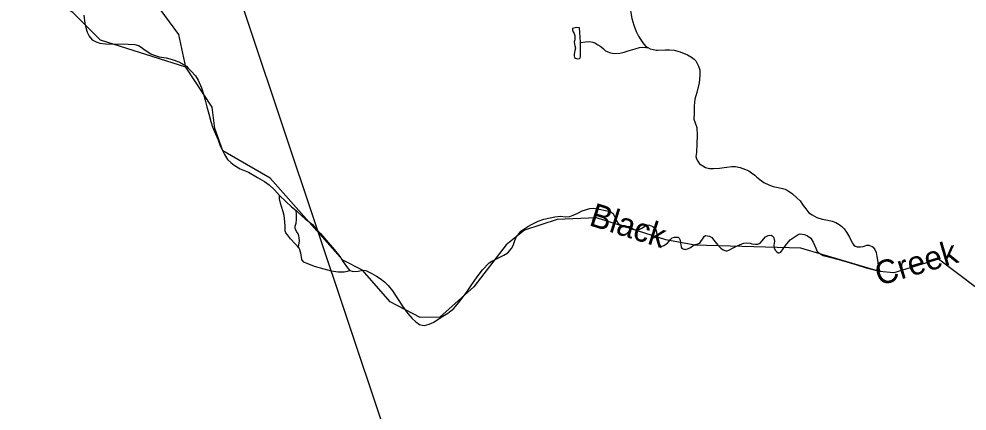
# Model space of a CAD drawing. Extents: x 2082433 to 2279600, y 546599 to 755198.
# Drawn here: x 2153161 to 2159193, y 625157 to 627650 of the extents above; entities that cross this region are included whole.
import ezdxf

# ---------------------------------------------------------------- set-up
doc = ezdxf.new("R2010")
doc.units = 0
for name, color, linetype in [('Exist Boundary Political Fire Districts', 7, 'Continuous'), ('Exist Hydrographic Creek Single Shore', 7, 'Continuous'), ('Exist Hydrographic Creek Single Shore Label', 7, 'Continuous'), ('Exist Hydrographic Misc Water Feature', 7, 'Continuous')]:
    doc.layers.add(name, color=color, linetype=linetype)

msp = doc.modelspace()

# ---------------------------------------------------------------- linework, layer by layer
at = {"layer": 'Exist Boundary Political Fire Districts'}
msp.add_lwpolyline([(2153751.2, 618762.9), (2155677.9, 624465.5), (2154003, 629468)], dxfattribs=at)
at = {"layer": 'Exist Hydrographic Creek Single Shore'}
for points in [[(2154221.5, 627344.2), (2154178.5, 627551.7), (2154028.6, 627751.6), (2153968.5, 627910.3), (2153975.5, 628257.9), (2154114.5, 628642.1), (2154453.5, 629035.5), (2154577.5, 629328.2), (2154576.5, 629446.3)], [(2154221.5, 627344.2), (2153679.6, 627516), (2153503.4, 627690.1), (2153411.6, 627747.7), (2153228.5, 627764.6), (2152503.4, 627759.6), (2152204.4, 627683.7), (2151820.3, 627806.3), (2151644.4, 627954.2), (2151410.4, 628070.5), (2151068.4, 628133.2), (2150709.4, 628340.5), (2150459.4, 628365.3), (2150300.5, 628404.6), (2150116.3, 628513.4), (2149924.4, 628687.8), (2149782.3, 628759.6), (2149523.3, 628751.8), (2149273.4, 628815.9), (2148940.4, 628730.7)], [(2159252.5, 625939.8), (2159010.6, 626121.9), (2158727.6, 626035.7), (2158635.5, 626044.1), (2158135.6, 626192.1), (2157460.6, 626212.3), (2157276.6, 626245.6), (2156834.5, 626385.8), (2156584.6, 626374.5), (2156376.4, 626306.6), (2156260.6, 626213.7), (2156054.5, 625945.7), (2155838.6, 625753.2), (2155713.5, 625752.5), (2155521.6, 625851.5), (2155345.4, 626051.9), (2155220.6, 626116.8), (2154758.6, 626637.9), (2154457.5, 626811.3), (2154407.5, 626953.3), (2154389.5, 627088.2), (2154221.5, 627344.2)]]:
    msp.add_lwpolyline(points, dxfattribs=at)
at = {"layer": 'Exist Hydrographic Misc Water Feature'}
for points in [[(2153573.2, 627673.6), (2153579.4, 627621.5), (2153585.8, 627595.4), (2153594, 627565.8), (2153607.9, 627539.8), (2153626.4, 627517.9), (2153652, 627503.9), (2153676.2, 627496.1), (2153712.1, 627492.3), (2153856.2, 627489.2), (2153898.3, 627487.3), (2153920.4, 627481.6), (2153938.2, 627471.5), (2153964.7, 627451.7), (2154000.4, 627428.1), (2154014.1, 627422), (2154052.5, 627410.1), (2154098.4, 627402.3), (2154134.7, 627392.8), (2154178.8, 627376.8), (2154226.9, 627349.2), (2154237.2, 627337.1)], [(2157052, 627704.8), (2157054, 627689.1), (2157060.2, 627652.9), (2157072.3, 627610.9), (2157086.6, 627569.4), (2157102.8, 627541.4), (2157117.2, 627517.4), (2157130.7, 627497.4), (2157147.1, 627477.5), (2157161, 627467.7)], [(2156733.3, 627499.2), (2156730.6, 627535.2), (2156726.7, 627593), (2156708.9, 627594.9), (2156682.9, 627589.1), (2156682.9, 627579), (2156686.5, 627569), (2156692.7, 627557.2), (2156697.2, 627543.1), (2156697.2, 627524.9), (2156697.2, 627517.1), (2156693.1, 627505.2), (2156695.4, 627491.1), (2156697.2, 627479.1), (2156701.5, 627465), (2156697.2, 627449), (2156693.7, 627425.2), (2156693.7, 627413), (2156695.8, 627405), (2156701.5, 627400.9), (2156713.6, 627397), (2156727.6, 627399.4), (2156731.7, 627403.2), (2156733.9, 627411.4), (2156733.3, 627499.2)], [(2156733.3, 627499.2), (2156764.9, 627505.3), (2156789.1, 627505.7), (2156811.4, 627501.5), (2156825.2, 627497.8), (2156843.2, 627485.8), (2156862.9, 627473.8), (2156879.3, 627460), (2156891.4, 627448), (2156907.4, 627440.4), (2156923.4, 627434.3), (2156949.6, 627430.3), (2156983.5, 627432.5), (2157011.4, 627438.8), (2157037.4, 627447.1), (2157081.5, 627459.1), (2157109.2, 627467.4), (2157127.4, 627469.6), (2157149.1, 627467.5), (2157161, 627467.7)], [(2157161, 627467.7), (2157177.2, 627459.6), (2157195.3, 627455.6), (2157217.2, 627451.9), (2157223.2, 627452.2), (2157273.2, 627454.4), (2157299.2, 627454.6), (2157329.2, 627450.8), (2157367.1, 627441), (2157413.5, 627421), (2157439.7, 627407.3), (2157455.5, 627395.2), (2157467.6, 627383.2), (2157477.8, 627363.5), (2157484, 627349.5), (2157492, 627325.6), (2157492.2, 627289.5), (2157488.5, 627243.4), (2157472.9, 627183.3), (2157460.8, 627139.3), (2157457.3, 627097.3), (2157455.5, 627073.6), (2157455.7, 627049.6), (2157453.4, 627013.5), (2157463.5, 626989.7), (2157473.9, 626959.7), (2157476.2, 626909.5), (2157474.4, 626855.4), (2157470.9, 626801.6), (2157467, 626775.4), (2157471.1, 626761.4), (2157479.5, 626745.5), (2157491.2, 626729.5), (2157511.1, 626716), (2157529.3, 626706), (2157553.5, 626699.9), (2157579.6, 626698.4), (2157617.3, 626700.4), (2157647.4, 626704.7), (2157665.1, 626706.9), (2157695.2, 626710.9), (2157719.4, 626710.9), (2157748.9, 626705.2), (2157783.2, 626693.6), (2157805.3, 626683.7), (2157821.5, 626671.5), (2157841.6, 626655.9), (2157855.8, 626644), (2157873.4, 626628), (2157899.8, 626610.2), (2157932, 626594.4), (2157960.1, 626584.5), (2157989.9, 626578.8), (2158017.7, 626570.9), (2158035.8, 626566.9), (2158054, 626556.8), (2158082.3, 626537.2), (2158112.5, 626511.2), (2158130.7, 626493.4), (2158150.4, 626463.6), (2158166.6, 626441.7), (2158186.5, 626417.6), (2158206.8, 626404), (2158236.7, 626388.1), (2158271, 626376.4), (2158307.1, 626370.6), (2158335, 626364.8), (2158358.7, 626354.7), (2158379.5, 626343), (2158395.2, 626330.9), (2158411.2, 626315.1), (2158425.4, 626295.1), (2158445.5, 626263.3), (2158461.7, 626227.2), (2158467.6, 626217.3), (2158471.7, 626211.4), (2158481.8, 626205.5), (2158493.9, 626201.6), (2158514, 626199.8), (2158531.6, 626203.6), (2158555.6, 626211.8), (2158567.5, 626212), (2158589.6, 626202.1), (2158595.8, 626198), (2158606.2, 626184.2), (2158614, 626164.4), (2158617.9, 626140.3), (2158622.2, 626116.5), (2158628.2, 626084.4), (2158634.5, 626056.3), (2158636.8, 626048.6)], [(2154237.2, 627337.1), (2154256.9, 627317.5), (2154283.3, 627287.5), (2154301.2, 627259.7), (2154321.7, 627211.6), (2154334.2, 627172), (2154345.7, 627134.2), (2154356.1, 627092), (2154368.4, 627045.9), (2154380.9, 626998.3), (2154392.6, 626964.4), (2154411.3, 626920.2), (2154427.5, 626880.5), (2154441.6, 626842.6), (2154468.1, 626788.8), (2154488.2, 626756.9), (2154508.3, 626736.9), (2154530.2, 626721), (2154568.4, 626697.4), (2154620.4, 626675.7), (2154678.7, 626642.2), (2154723.2, 626616.4), (2154752.7, 626594.5), (2154787.4, 626562.5), (2154819.1, 626526.8)], [(2154819.1, 626526.8), (2154859.3, 626489.1), (2154895.6, 626455.2), (2154923.7, 626431.6)], [(2154937.3, 626199.5), (2154932.7, 626205.5), (2154919, 626219.7), (2154888.9, 626251.5), (2154868.6, 626277.2), (2154858.7, 626289.3), (2154854.2, 626302.9), (2154854.4, 626317.1), (2154854.4, 626334.9), (2154850.1, 626381), (2154847.6, 626399.2), (2154841.9, 626422.8), (2154831.9, 626456.8), (2154825.7, 626478.8), (2154819.3, 626507), (2154819.1, 626526.8)], [(2154937.3, 626199.5), (2154939.3, 626203.7), (2154940.9, 626213.6), (2154943, 626223.8), (2154944.8, 626239.8), (2154942.6, 626257.5), (2154940.7, 626271.6), (2154936.8, 626283.6), (2154928.6, 626295.3), (2154920.6, 626311.5), (2154918.6, 626321.6), (2154918.2, 626325.3), (2154918.4, 626331.3), (2154920.6, 626339.5), (2154924.3, 626351.5), (2154926.4, 626371.5), (2154927.6, 626407.4), (2154923.7, 626431.6)], [(2154923.7, 626431.6), (2154937.9, 626419.7), (2154982.2, 626379.7), (2155008.2, 626359.9), (2155028.1, 626341.9), (2155056.6, 626308.1), (2155078.3, 626286.5), (2155127.1, 626228.9), (2155166.9, 626183), (2155201.4, 626138.9), (2155223.3, 626105.2), (2155251.4, 626067.3), (2155265.9, 626049.6)], [(2155265.9, 626049.6), (2155279.7, 626045.5), (2155292.2, 626043.7), (2155318, 626045.8), (2155348, 626051.8), (2155367.7, 626050.1), (2155405.8, 626032.2), (2155435.9, 626014.2), (2155458.1, 625998.7), (2155486.2, 625978.6), (2155510.2, 625954.8), (2155536.6, 625921.2), (2155568.6, 625873.3), (2155601, 625823.4), (2155633.2, 625779.6), (2155661.5, 625745.7), (2155685.5, 625723.8), (2155709.7, 625708), (2155725.7, 625702.3), (2155741.7, 625700.3), (2155771.4, 625708.4), (2155799.7, 625722.4), (2155847.3, 625752.9), (2155889.1, 625779), (2155926.8, 625809.4), (2155956.6, 625845.5), (2155980.4, 625873.5), (2156011.9, 625917.8), (2156038, 625954), (2156075.9, 626010), (2156109.1, 626054.4), (2156153, 626098.4), (2156169, 626110.6), (2156183.4, 626116.6), (2156199.1, 626124.7), (2156220.7, 626134.8), (2156244.9, 626147), (2156270.9, 626163), (2156294.7, 626191), (2156304.5, 626209.4), (2156316.2, 626241.3), (2156324.2, 626261.6), (2156334.3, 626275.5), (2156354, 626299.7), (2156397.8, 626329.9), (2156425.9, 626345.9), (2156463.9, 626364.1), (2156499.3, 626376.2), (2156539.5, 626384.3), (2156569.5, 626390.7), (2156605.3, 626395.1), (2156637.5, 626391), (2156665.4, 626393.3), (2156687.2, 626401.4), (2156717.1, 626415.5), (2156745, 626429.5), (2156793.4, 626444.1), (2156817.2, 626446.2), (2156853.1, 626440.4), (2156891.4, 626432.5), (2156925.4, 626422.5), (2156937.1, 626414.6), (2156943.1, 626406.8), (2156955.4, 626382.7), (2156961.5, 626366.8), (2156973.4, 626349.2), (2156983.5, 626343.2), (2156999.5, 626337.1), (2157019.8, 626333.2), (2157045.4, 626329.3), (2157059.9, 626319.4), (2157069.6, 626313.5), (2157083.7, 626309.8), (2157107.5, 626311.9), (2157127.4, 626321.8), (2157145.7, 626334), (2157155.5, 626339.9), (2157171.5, 626338.3), (2157193.4, 626330.1), (2157207.6, 626320.3), (2157211.9, 626310.3), (2157217.8, 626292.3), (2157230.1, 626238.5), (2157234.4, 626218.5), (2157235.9, 626212.6), (2157240, 626206.7), (2157248.4, 626202.6), (2157264.2, 626208.7), (2157285.9, 626224.9), (2157307.9, 626248.7), (2157315.9, 626258.8), (2157331.8, 626262.9), (2157355.8, 626261.3), (2157362, 626255.1), (2157368.1, 626243.3), (2157370.2, 626227.1), (2157373.9, 626201.4), (2157376.3, 626195.4), (2157386, 626187.4), (2157400.3, 626183.6)], [(2157400.3, 626183.6), (2157420.4, 626189.5), (2157434, 626197.6), (2157448.1, 626207.6), (2157456.3, 626213.7), (2157462.1, 626215.6), (2157480.3, 626219.8), (2157492, 626224.1), (2157500, 626233.8), (2157510, 626250.2), (2157519.9, 626266.1), (2157529.7, 626271.9), (2157553.7, 626268.3), (2157567.9, 626260.5), (2157582.2, 626242.5), (2157606.2, 626210.5), (2157626.3, 626192.9), (2157640.2, 626182.6), (2157658.1, 626175.1), (2157666.3, 626175.1), (2157676.1, 626178.8), (2157708.1, 626197.1), (2157749.9, 626215.5), (2157772.1, 626223.5), (2157789.9, 626225.7), (2157812.1, 626223.6), (2157824.2, 626219.7), (2157845.9, 626218), (2157862.1, 626218), (2157875.9, 626224.1), (2157887.9, 626236), (2157909.7, 626264.4), (2157927.7, 626272.2), (2157945.8, 626274.3), (2157959.9, 626266.5), (2157963.6, 626258.6), (2157967.9, 626236.5), (2157964.2, 626210.7), (2157965.7, 626194.7), (2157972.4, 626178.7), (2157982.3, 626168.7), (2157990.3, 626163), (2157998.3, 626162.6), (2158008.3, 626166.7), (2158037.8, 626208.9), (2158067.8, 626245.4), (2158099.8, 626267.3), (2158119.2, 626279.4), (2158131.3, 626283.6), (2158159.2, 626279.8), (2158177.5, 626271.8), (2158199.4, 626255.9), (2158213.8, 626229.8), (2158230.2, 626192), (2158240, 626170.2), (2158256.4, 626158.4), (2158278.2, 626146.2), (2158328.2, 626132.6), (2158392.4, 626115.2), (2158484.2, 626087.5), (2158550.3, 626067.8), (2158618.8, 626050.1), (2158636.8, 626048.6)], [(2154937.3, 626199.5), (2154943.2, 626189.7), (2154951.4, 626161.7), (2154957.6, 626119.8), (2154969.6, 626105.8), (2154991.4, 626096), (2155039.4, 626078.2), (2155099.9, 626060.6), (2155148, 626048.8), (2155191.7, 626041), (2155229.7, 626041.3), (2155252, 626045.3), (2155265.9, 626049.6)]]:
    msp.add_lwpolyline(points, dxfattribs=at)

# ---------------------------------------------------------------- texts
at = {"layer": 'Exist Hydrographic Creek Single Shore Label'}
for s, rotation, p in [('Black', 342.45795, (2156781.2, 626339.7)), ('Creek', 16.43582, (2158632.6, 625951.9))]:
    msp.add_text(s, height=150, rotation=rotation, dxfattribs=at).set_placement(p)

doc.saveas('drawing.dxf')
